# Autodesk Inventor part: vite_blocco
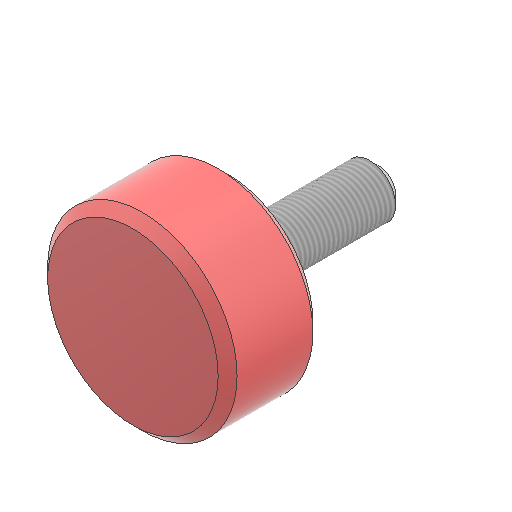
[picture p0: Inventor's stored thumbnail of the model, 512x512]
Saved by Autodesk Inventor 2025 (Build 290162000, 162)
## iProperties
Created: 2025-09
Part Number: vite_blocco
Material: Generico
Document SubType Name: Modeling
Designer: Ryzen5700u
Density: 1 g/cm^3
Appearance: Default
Author: Ryzen5700u
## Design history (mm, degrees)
sketch "Schizzo1"
  geometry: C1 r 2.75 at (22, -2.5) reference; 1 further point
extrude "Estrusione1" new body sketch "Schizzo1" distance "d0" = 16; taper "d1" = 0 deg
sketch "Schizzo2"
  geometry: C1 r 10 at (0, 0); 1 further point
  constraints: 1 centre point
  dimensions: "d2" = 20 diameter of C1
extrude "Estrusione2" join sketch "Schizzo2" distance "d3" = 10; taper "d4" = 0 deg
chamfer "Smusso1" distance "d5" = 1; stored, may be unused: second distance "d6" = 2, angle "d7" = 45 deg
chamfer "Smusso2" distance "d8" = 1; stored, may be unused: second distance "d9" = 2, angle "d10" = 45 deg
feature "Filettatura1" dims "d11" = 14, "d12" = 0
node "Solido1"
node "Riferimento1"
